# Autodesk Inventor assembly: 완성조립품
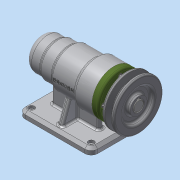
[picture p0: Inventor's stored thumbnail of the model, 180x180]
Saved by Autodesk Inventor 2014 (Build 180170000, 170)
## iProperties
Created: 2016-06
Part Number: 완성조립품
Document SubType Name: Assembly
Designer: 406-017
Author: 406-017
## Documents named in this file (12)
- C:\Users\406-017\Desktop\460607V1015\완성조립품.iam
- C:\Users\406-017\Desktop\460607V1015\V벨트풀리.ipt
- C:\Users\406-017\Desktop\460607V1015\멈춤나사 M3x8.ipt
- C:\Users\406-017\Desktop\460607V1015\베어링 6004.ipt
- C:\Users\406-017\Desktop\460607V1015\베어링 51202.ipt
- C:\Users\406-017\Desktop\460607V1015\본체.ipt
- C:\Users\406-017\Desktop\460607V1015\볼트 M4 x 12.ipt
- C:\Users\406-017\Desktop\460607V1015\어댑터슬리브.ipt
- C:\Users\406-017\Desktop\460607V1015\오일 실.ipt
- C:\Users\406-017\Desktop\460607V1015\축.ipt
- C:\Users\406-017\Desktop\460607V1015\커버.ipt
- C:\Users\406-017\Desktop\460607V1015\키 5 x 5 x 16.ipt
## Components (6 placed, 2 different names)
1. V벨트풀리:1 — 플러쉬:1
2. ISO 4762 M4 x 12:2 — 플러쉬:2
3. ISO 4762 M4 x 12:1
4. ISO 4762 M4 x 12:3
5. ISO 4762 M4 x 12:4
6. ISO 4762 M4 x 12:5
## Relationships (2: Flush 2)
- 플러쉬:1 [Flush]: V벨트풀리:1
- 플러쉬:2 [Flush]: ISO 4762 M4 x 12:2
